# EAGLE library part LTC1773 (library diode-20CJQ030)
Linear Tech's LTC1773 Synchronous Step-Down DC/DC Controller Description: The LTC®1773 is a current mode synchronous buck regulator controller that drives external complementary power MOSFETs using a fixed frequency architecture. The operating supply range is from 2.65V to 8.5V, making it suitable for 1- or 2-cell lithium-ion battery powered applications. Burst ModeTM operation provides high efficiency at low load currents. 100% duty cycle provides low dropout operation which extends operating time in battery- operated systems. The operating frequency is internally set at 550kHz, allowing the use of small surface mount inductors. For switching- noise sensitive applications, it can be synchronized up to 750kHz. Peak current limit is user programmable with an external high side sense resistor. A SYNC/FCB control pin guarantees regulation of secondary windings regardless of load on the main output by forcing continuous operation. Burst Mode operation is inhibited during synchronization or when the SYNC/FCB pin is pulled low to reduce noise and RF interference. Soft start is provided by an external capacitor. Synchronous rectification increases efficiency and eliminates the need for a Schottky diode, saving components and board space. Features: High Efficiency: Up to 95% Constant Frequency 550kHz Operation VIN from 2.65V to 8.5V VOUT from 0.8V to VIN OPTI-LOOPTM Compensation Minimizes COUT Synchronizable up to 750kHz Selectable Burst Mode Operation Low Quiescent Current: 80mA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
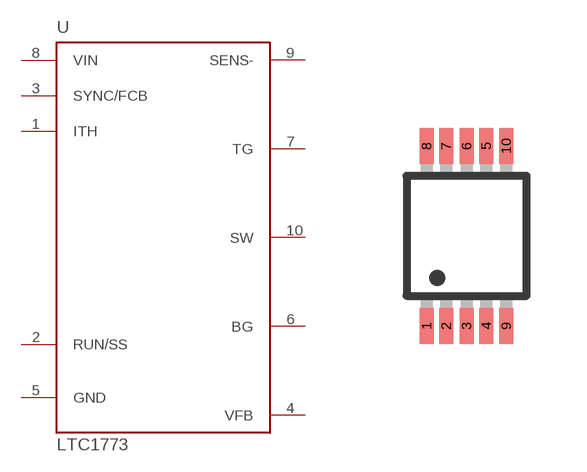
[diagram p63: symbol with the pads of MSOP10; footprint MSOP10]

Designator prefix U

## LTC1773  [MSOP10]
1  ITH  in
2  RUN/SS  in
3  SYNC/FCB  in
4  VFB  in
5  GND  pwr
6  BG  out
7  TG  out
8  VIN  pwr
9  SENS-  in
10  SW  out

## Footprint MSOP10 (pad centres in mm)
MSOP10
smd 0.35 x 0.9: 1 -1,-2.25; 2 -0.51,-2.25; 3 0,-2.25; 4 0.49,-2.25; 5 0.49,2.25; 6 0,2.25; 7 -0.51,2.25; 8 -1,2.25; 9 0.99,-2.25; 10 0.99,2.25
